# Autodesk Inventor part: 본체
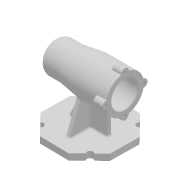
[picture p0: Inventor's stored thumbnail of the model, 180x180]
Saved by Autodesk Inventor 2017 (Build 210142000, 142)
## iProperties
Created: 2019-12
Part Number: 본체
Material: Generic
Document SubType Name: Modeling
Designer: 5-02-le
Density: 1 g/cm^3
Appearance: Default
Author: 5-02-le
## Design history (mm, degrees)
sketch "스케치2"
  geometry: L1 (23.927, 55.692)-(56.299, 22.461); L2 (56.299, 22.461)-(55.692, -23.927); L3 (55.692, -23.927)-(22.461, -56.299); L4 (22.461, -56.299)-(-23.927, -55.692); L5 (-23.927, -55.692)-(-56.299, -22.461); L6 (-56.299, -22.461)-(-55.692, 23.927); L7 (-55.692, 23.927)-(-22.461, 56.299); L8 (-22.461, 56.299)-(23.927, 55.692); 2 further points
  constraints: 16 end point, 17 other
  dimensions: "d1" = 56 distance from line of L2 point (0, 0)
extrude "돌출1" new body sketch "스케치2" stored distance "d2" = 10; taper "d3" = 0 deg
sketch "스케치3"
  geometry: L1 (56.299, 75)-(-55.701, 75); L2 (56.299, 5)-(56.299, -5) reference; L3 (-55.692, -5)-(-22.461, -5) reference; L4 (56.299, 75)-(56.299, 100); L5 (56.299, 100)-(27.912, 100); L6 (27.912, 100)-(-4.425, 105); L7 (-55.701, 75)-(-55.701, 105); L8 (-4.425, 105)-(-55.701, 105); 1 further point
  constraints: 12 end point, 2 horizontal, 2 vertical, 1 perpendicular, 1 point on line
  dimensions: "d4" = 80 distance between parallel lines of L3 L1; "d5" = 50 diameter of L5 L1; "d6" = 60 diameter of L8 L1; "d7" = 112 distance between parallel lines of L7 L4
revolve "회전1" sketch "스케치3" stored, may be unused: angle "d8" = 90 deg
sketch "스케치4"
  geometry: L1 (30.692, 5)-(10.133, 49.089); L2 (10.133, 49.089)-(-31.299, 49.089); L3 (-31.299, 49.089)-(-31.299, 5); L4 (-31.299, 5)-(30.692, 5); L5 (55.692, 5)-(55.692, -5) reference; L6 (-56.299, 5)-(-56.299, -5) reference; L7 (22.461, 5)-(55.692, 5) reference; 1 further point
  constraints: 8 end point, 2 perpendicular
  dimensions: "d9" = 25 distance from line of L1.start L5; "d10" = 25 distance from line of L6 L3.end; "d11" = 115 deg angle of L7 L1
extrude "돌출2" join sketch "스케치4" stored distance "d12" = 8; taper "d13" = 0 deg
sketch "스케치5"
  geometry: L1 (-35.692, 5)-(-17.068, 56.167); L2 (-17.068, 56.167)-(17.675, 56.167); L3 (17.675, 56.167)-(36.299, 5); L4 (56.299, 5)-(23.927, 5) reference; L5 (-35.692, 5)-(36.299, 5); L6 (-22.461, 5)-(-55.692, 5) reference; L7 (-55.692, 5)-(-55.692, -5) reference; L8 (56.299, 5)-(56.299, -5) reference; 1 further point
  constraints: 8 end point, 1 collinear, 1 horizontal, 1 point on line
  dimensions: "d14" = 20 distance from line of L7 L1.start; "d15" = 20 distance from line of L8 L3.end; "d16" = 110 deg angle of L4 L3; "d17" = 110 deg angle of L1 L6
extrude "돌출3" join sketch "스케치5" stored distance "d18" = 8; taper "d19" = 0 deg
sketch "스케치6"
  geometry: L1 (56.299, 50)-(56.299, 100) reference; L2 (56.299, 75)-(-57.001, 75); L3 (50.299, 75)-(47.299, 75); L4 (47.299, 75)-(47.299, 85.5); L5 (47.299, 85.5)-(50.299, 85.5); L6 (50.299, 85.5)-(50.299, 75); L7 (47.299, 75)-(43.299, 75); L8 (43.299, 75)-(43.299, 91); L9 (43.299, 91)-(47.299, 91); L10 (47.299, 91)-(47.299, 75); L11 (43.299, 75)-(25.299, 75); L12 (25.299, 75)-(25.299, 92.5); L13 (25.299, 92.5)-(43.299, 92.5); L14 (43.299, 92.5)-(43.299, 75); L15 (25.299, 75)-(13.299, 75); L16 (13.299, 75)-(13.299, 96); L17 (13.299, 96)-(25.299, 96); L18 (25.299, 96)-(25.299, 75); L19 (13.299, 75)-(-40.701, 75); L20 (-40.701, 75)-(-40.701, 99); L21 (-40.701, 99)-(13.299, 99); L22 (13.299, 99)-(13.299, 75); L23 (-40.701, 75)-(-55.701, 75); L24 (-40.701, 92.5)-(-40.701, 75); L25 (-55.701, 45)-(-55.701, 105) reference; L26 (-40.701, 75)-(-55.701, 75); L27 (-55.701, 75)-(-55.701, 96); L28 (-55.701, 96)-(-40.701, 96); L29 (-40.701, 96)-(-40.701, 75); 1 further point
  constraints: 54 end point, 12 parallel, 7 horizontal, 6 perpendicular, 2 point on line, 1 midpoint
  dimensions: "d20" = 3 distance between parallel lines of L4 L6; "d21" = 4 distance between parallel lines of L8 L10; "d22" = 18 distance between parallel lines of L18 L14; "d23" = 12 distance between parallel lines of L22 L18; "d24" = 54 distance between parallel lines of L20 L22; "d26" = 21 diameter of L5 L2; "d27" = 32 diameter of L9 L2; "d28" = 35 diameter of L13 L2; "d29" = 42 diameter of L17 L2; "d30" = 48 diameter of L21 L2; "d32" = 42 diameter of L28 L2; "d33" = 15 distance between parallel lines of L25 L20
revolve "회전2" sketch "스케치6" stored, may be unused: angle "d34" = 90 deg
sketch "스케치7"
  geometry: L1 (0, 0)-(-30, 0); C1 r 6 at (-30, 0); 1 further point
  constraints: 2 end point, 1 centre point, 1 coincident, 1 horizontal
  dimensions: "d35" = 12 diameter of C1
extrude "돌출4" join sketch "스케치7" distance "d36" = 16; taper "d37" = 0 deg
fillet "모깎기1" dims "d38" = 3
fillet "모깎기2" dims "d39" = 1
sketch "스케치8"
  geometry: 2 further points
hole "구멍1" sketch "스케치8" at (0, -0.048) diameter "d43" = 3.242; stored, may be unused: countersink angle "d47" = 90 deg, drill point angle "d49" = 118 deg; dims "d44" = 8, "d45" = 4, "d46" = 2, "d48" = 11.8
sketch "스케치10"
  geometry: L1 (0, 0)-(-39.601, 39.601); L2 (0, 0)-(-39.601, -39.601); L3 (0, 0)-(39.601, 39.601); L4 (0, 0)-(39.601, -39.601); L5 (0, 0)-(0, 56.005); C1 r 5 at (-39.601, 39.601); C2 r 5 at (-39.601, -39.601); C3 r 5 at (39.601, 39.601); C4 r 5 at (39.601, -39.601)
  constraints: 10 end point, 4 centre point, 4 coincident, 1 vertical
  dimensions: "d54" = 10 diameter of C1; "d56" = 90 deg angle of L1 L2; "d57" = 10 diameter of C2; "d58" = 45 deg angle of L3 L5; "d59" = 90 deg angle of L4 L3; "d60" = 10 diameter of C4; "d61" = 10 diameter of C3
extrude "돌출5" cut sketch "스케치10" stored distance "d62" = 16; taper "d63" = 0 deg
fillet "모깎기3" dims "d64" = 10
fillet "모깎기4" dims "d65" = 1
fillet "모깎기5" dims "d66" = 3
fillet "모깎기6" dims "d67" = 3
fillet "모깎기7" dims "d68" = 3
chamfer "모따기1" distance "d69" = 1; stored, may be unused: second distance "d70" = 2, angle "d71" = 45 deg
fillet "모깎기8" dims "d72" = 0.3
fillet "모깎기9" dims "d73" = 3
node "솔리드1"
pattern_circular "원형 패턴1" dims angle "d41" = 360 deg
pattern_circular "원형 패턴2" dims angle "d51" = 360 deg
